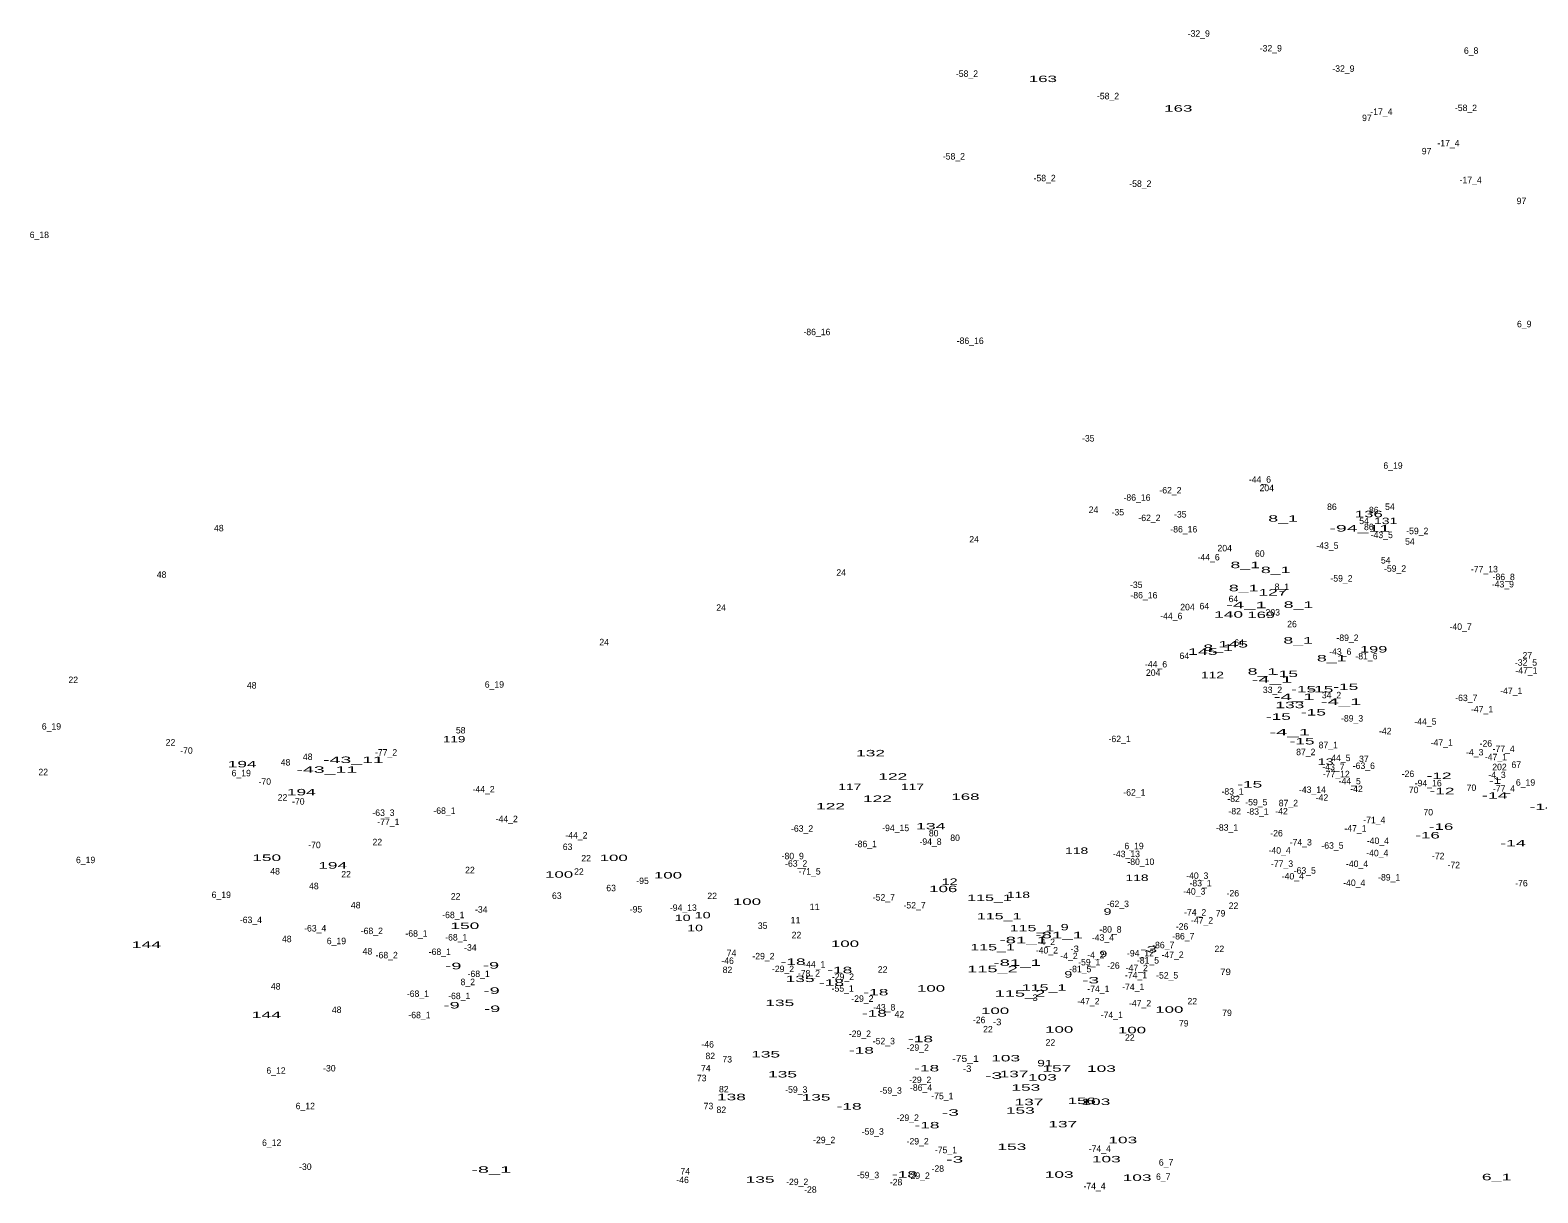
# Model space of a CAD drawing. Extents: x -659624 to -656248, y -1006345 to -1003555.
# Drawn here: x -658653 to -657721, y -1005012 to -1004293 of the extents above; entities that cross this region are included whole.
import ezdxf
from ezdxf.enums import TextEntityAlignment as Align

# ---------------------------------------------------------------- set-up
doc = ezdxf.new("R2010")
doc.units = 0
doc.header["$LTSCALE"] = 1.6
doc.layers.add('24', color=7, linetype='Continuous')

msp = doc.modelspace()

# ---------------------------------------------------------------- texts
at = {"layer": '24'}
for s, p in [('-32_9', (-657930.358, -1004297.46)), ('-32_9', (-657885.848, -1004306.59)), ('6_8', (-657762.051, -1004308.04)), ('-32_9', (-657840.968, -1004319.15)), ('-58_2', (-658073.602, -1004322.3)), ('-58_2', (-657986.432, -1004336.13)), ('-17_4', (-657817.496, -1004345.8)), ('-58_2', (-657765.232, -1004343.43)), ('97', (-657826.468, -1004349.62)), ('-17_4', (-657776.036, -1004365.21)), ('-58_2', (-658081.672, -1004373.38)), ('97', (-657789.558, -1004370.19)), ('-58_2', (-658025.602, -1004386.83)), ('-58_2', (-657966.462, -1004390.29)), ('-17_4', (-657762.346, -1004388.04)), ('97', (-657730.928, -1004400.96)), ('6_18', (-658646.834, -1004421.92)), ('6_9', (-657729.257, -1004477.04)), ('-86_16', (-658166.317, -1004481.95)), ('-86_16', (-658071.597, -1004487.39)), ('-35', (-657998.635, -1004547.69)), ('6_19', (-657810.32, -1004564.54)), ('-62_2', (-657947.868, -1004579.77)), ('-44_6', (-657892.556, -1004573.1)), ('204', (-657888.355, -1004578.38)), ('-86_16', (-657968.527, -1004584.28)), ('86', (-657848.083, -1004589.99)), ('54', (-657812.251, -1004589.97)), ('24', (-657995.401, -1004591.84)), ('-35', (-657980.385, -1004593.35)), ('-62_2', (-657960.828, -1004596.87)), ('-35', (-657941.775, -1004594.68)), ('54', (-657828.231, -1004598.73)), ('86', (-657822.223, -1004592.03)), ('48', (-658535.911, -1004603.2)), ('-86_16', (-657939.607, -1004603.89)), ('86', (-657825.273, -1004602.46)), ('-43_5', (-657817.267, -1004607.39)), ('-59_2', (-657795.318, -1004604.95)), ('24', (-658069.191, -1004610.09)), ('204', (-657914.315, -1004615.57)), ('-43_5', (-657850.857, -1004613.98)), ('54', (-657799.891, -1004611.47)), ('-44_6', (-657924.276, -1004621.18)), ('60', (-657892.637, -1004618.92)), ('54', (-657814.821, -1004623.08)), ('48', (-658571.281, -1004631.93)), ('24', (-658151.341, -1004630.65)), ('-59_2', (-657842.168, -1004634.24)), ('-59_2', (-657809.048, -1004628.19)), ('-77_13', (-657753.867, -1004628.55)), ('-86_8', (-657741.918, -1004633.36)), ('-35', (-657968.975, -1004638.24)), ('-86_16', (-657964.257, -1004644.67)), ('8_1', (-657879.03, -1004639.46)), ('-43_9', (-657742.442, -1004637.87)), ('24', (-658225.531, -1004652.33)), ('204', (-657937.335, -1004652)), ('64', (-657926.917, -1004651.4)), ('64', (-657908.937, -1004646.93)), ('203', (-657884.631, -1004655.24)), ('-44_6', (-657947.336, -1004657.52)), ('26', (-657872.743, -1004662.51)), ('-40_7', (-657768.556, -1004664.1)), ('24', (-658297.791, -1004673.64)), ('64', (-657905.417, -1004673.93)), ('-89_2', (-657838.438, -1004670.98)), ('64', (-657939.277, -1004682.12)), ('-43_6', (-657842.912, -1004679.52)), ('-81_6', (-657826.732, -1004682.36)), ('27', (-657727.313, -1004681.8)), ('-44_6', (-657956.756, -1004687.33)), ('204', (-657958.535, -1004692.53)), ('-32_5', (-657728.152, -1004686.27)), ('-47_1', (-657727.856, -1004691.19)), ('22', (-658625.877, -1004696.97)), ('48', (-658515.601, -1004700.39)), ('6_19', (-658365.63, -1004699.85)), ('33_2', (-657884.785, -1004703.16)), ('34_2', (-657848.32, -1004706.41)), ('-63_7', (-657765.024, -1004708.13)), ('-47_1', (-657737.256, -1004703.8)), ('-89_3', (-657835.608, -1004720.78)), ('-47_1', (-657755.286, -1004715.14)), ('6_19', (-658639.35, -1004725.77)), ('58', (-658386.457, -1004728.13)), ('-42', (-657815.099, -1004728.65)), ('-44_5', (-657790.301, -1004722.73)), ('22', (-658565.787, -1004735.6)), ('-62_1', (-657979.262, -1004733.51)), ('87_1', (-657850.334, -1004737.28)), ('-47_1', (-657780.206, -1004735.7)), ('-26', (-657752.96, -1004736.29)), ('-77_4', (-657741.938, -1004739.6)), ('-70', (-658555.924, -1004740.66)), ('48', (-658494.681, -1004747.95)), ('48', (-658480.991, -1004744.53)), ('-77_2', (-658432.564, -1004741.83)), ('87_2', (-657864.23, -1004741.56)), ('-44_5', (-657843.441, -1004745.23)), ('37', (-657828.343, -1004745.81)), ('-4_3', (-657759.818, -1004741.7)), ('-47_1', (-657746.766, -1004744.71)), ('22', (-658644.427, -1004753.95)), ('6_19', (-658522.08, -1004754.61)), ('-43_7', (-657847.122, -1004750.81)), ('-77_12', (-657845.387, -1004755.22)), ('-63_6', (-657828.343, -1004750.09)), ('-26', (-657801.09, -1004755.05)), ('-4_3', (-657746.028, -1004755.71)), ('202', (-657744.521, -1004750.86)), ('67', (-657734.158, -1004749.43)), ('-70', (-658507.534, -1004759.86)), ('-44_2', (-658372.311, -1004764.6)), ('-62_1', (-657970.142, -1004766.54)), ('-83_1', (-657909.496, -1004765.97)), ('-43_14', (-657860.135, -1004764.9)), ('-44_5', (-657837.091, -1004759.58)), ('-42', (-657832.879, -1004764.33)), ('70', (-657797.587, -1004765.02)), ('-94_16', (-657788.571, -1004760.82)), ('70', (-657761.837, -1004763.68)), ('-77_4', (-657741.748, -1004764.16)), ('6_19', (-657728.43, -1004760.4)), ('22', (-658496.557, -1004769.65)), ('-70', (-658486.794, -1004772.16)), ('-82', (-657908.835, -1004770.49)), ('-59_5', (-657894.778, -1004772.61)), ('87_2', (-657874.97, -1004773.15)), ('-42', (-657854.229, -1004769.72)), ('-63_3', (-658434.188, -1004779.12)), ('-77_1', (-658431.167, -1004784.8)), ('-68_1', (-658396.492, -1004777.86)), ('-44_2', (-658358.001, -1004782.97)), ('-82', (-657908.155, -1004778.16)), ('-83_1', (-657894.036, -1004778.35)), ('-42', (-657879.209, -1004778.18)), ('-71_4', (-657821.876, -1004783.62)), ('70', (-657788.557, -1004778.81)), ('-44_2', (-658314.931, -1004793.06)), ('-63_2', (-658175.498, -1004788.88)), ('-94_15', (-658117.666, -1004788.52)), ('80', (-658094.151, -1004791.77)), ('80', (-658080.931, -1004794.62)), ('-83_1', (-657912.866, -1004788.26)), ('-26', (-657882.3, -1004791.77)), ('-47_1', (-657833.516, -1004788.81)), ('-70', (-658476.814, -1004799.05)), ('22', (-658437.977, -1004797.24)), ('63', (-658320.413, -1004800.17)), ('-86_1', (-658136.092, -1004798.43)), ('-94_8', (-658096.122, -1004796.98)), ('-43_13', (-657975.03, -1004804.59)), ('6_19', (-657970.34, -1004799.69)), ('-40_4', (-657880.405, -1004802.4)), ('-74_3', (-657867.322, -1004797.36)), ('-63_5', (-657847.748, -1004799.37)), ('-40_4', (-657820.035, -1004804.04)), ('-40_4', (-657819.655, -1004796.44)), ('6_19', (-658618.23, -1004808.3)), ('22', (-658308.937, -1004807.23)), ('-80_9', (-658181.272, -1004805.9)), ('-63_2', (-658179.148, -1004810.49)), ('-80_10', (-657966.154, -1004809.43)), ('-77_3', (-657878.904, -1004810.63)), ('-40_4', (-657832.535, -1004810.67)), ('-72', (-657782.381, -1004805.88)), ('-72', (-657772.781, -1004811.45)), ('48', (-658501.151, -1004815.3)), ('22', (-658457.287, -1004817.12)), ('22', (-658380.737, -1004814.55)), ('22', (-658313.407, -1004815.5)), ('-95', (-658274.08, -1004821.23)), ('-71_5', (-658170.852, -1004815.35)), ('-40_3', (-657931.301, -1004818.05)), ('-83_1', (-657929.256, -1004822.62)), ('-40_4', (-657872.235, -1004818.37)), ('-63_5', (-657864.838, -1004814.83)), ('-40_4', (-657834.265, -1004822.4)), ('-89_1', (-657812.702, -1004819.04)), ('-76', (-657730.965, -1004822.67)), ('6_19', (-658534.42, -1004829.84)), ('48', (-658477.191, -1004824.43)), ('22', (-658389.577, -1004830.82)), ('63', (-658327.073, -1004830.42)), ('63', (-658293.503, -1004825.66)), ('22', (-658231.057, -1004830.54)), ('-52_7', (-658124.968, -1004831.41)), ('-40_3', (-657933.131, -1004827.74)), ('-26', (-657909.31, -1004828.87)), ('48', (-658451.321, -1004836.23)), ('-68_1', (-658391.022, -1004842.3)), ('-34', (-658373.729, -1004838.91)), ('-95', (-658278.15, -1004838.81)), ('-94_13', (-658248.906, -1004837.83)), ('-52_7', (-658105.968, -1004836.31)), ('-62_3', (-657980.348, -1004835.47)), ('-74_2', (-657932.582, -1004840.68)), ('79', (-657916.898, -1004841.27)), ('22', (-657908.877, -1004836.61)), ('-63_4', (-658516.112, -1004845.35)), ('-63_4', (-658476.372, -1004850.54)), ('35', (-658199.867, -1004848.94)), ('-80_8', (-657984.906, -1004851.24)), ('-26', (-657940.69, -1004849.42)), ('-47_2', (-657928.322, -1004845.67)), ('48', (-658493.921, -1004857.15)), ('6_19', (-658463.24, -1004858.38)), ('-68_2', (-658441.368, -1004852.15)), ('-68_1', (-658413.772, -1004853.73)), ('-68_1', (-658389.192, -1004856.13)), ('22', (-658178.947, -1004854.7)), ('-4_2', (-658024.538, -1004858.96)), ('-43_4', (-657989.561, -1004856.24)), ('-86_7', (-657952.314, -1004860.9)), ('-86_7', (-657939.894, -1004855.46)), ('48', (-658444.091, -1004864.76)), ('-68_2', (-658432.158, -1004867.13)), ('-68_1', (-658399.372, -1004865.06)), ('-34', (-658380.479, -1004862.41)), ('74', (-658219.087, -1004865.83)), ('-29_2', (-658199.358, -1004867.76)), ('-40_2', (-658024.211, -1004864.15)), ('-4_2', (-658010.558, -1004867.62)), ('-4_2', (-657993.958, -1004867.08)), ('-94_12', (-657966.396, -1004865.96)), ('-81_5', (-657961.756, -1004870.35)), ('-47_2', (-657946.552, -1004866.91)), ('22', (-657917.627, -1004863.25)), ('-68_1', (-658375.362, -1004878.71)), ('-46', (-658221.525, -1004870.59)), ('82', (-658221.607, -1004876.23)), ('-29_2', (-658187.278, -1004875.65)), ('-78_2', (-658171.268, -1004878.4)), ('-44_1', (-658167.955, -1004872.85)), ('22', (-658125.697, -1004876.01)), ('-81_5', (-658003.586, -1004875.74)), ('-59_1', (-657998.042, -1004871.5)), ('-26', (-657983.1, -1004873.58)), ('-74_1', (-657969.156, -1004879.48)), ('-47_2', (-657968.652, -1004875.06)), ('-52_5', (-657949.882, -1004879.63)), ('48', (-658500.771, -1004886.45)), ('8_2', (-658382.076, -1004883.73)), ('-55_1', (-658150.396, -1004887.72)), ('-29_2', (-658150.248, -1004880.51)), ('-74_1', (-657992.386, -1004887.93)), ('-74_1', (-657970.876, -1004886.78)), ('-68_1', (-658412.902, -1004891)), ('-68_1', (-658387.362, -1004892.35)), ('-29_2', (-658138.218, -1004894.02)), ('-47_2', (-657998.512, -1004895.61)), ('-47_2', (-657966.612, -1004896.88)), ('22', (-657934.367, -1004895.59)), ('48', (-658463.111, -1004900.91)), ('-68_1', (-658411.942, -1004904.16)), ('-43_8', (-658124.737, -1004899.39)), ('42', (-658115.381, -1004903.72)), ('-26', (-658066.07, -1004907.21)), ('-74_1', (-657984.126, -1004904.06)), ('79', (-657912.908, -1004902.79)), ('-29_2', (-658139.778, -1004915.75)), ('22', (-658060.647, -1004912.9)), ('79', (-657939.628, -1004909.26)), ('-46', (-658233.835, -1004922.27)), ('-52_3', (-658124.982, -1004920.27)), ('-29_2', (-658103.978, -1004924.26)), ('22', (-658022.037, -1004921.09)), ('22', (-657972.967, -1004918.04)), ('82', (-658232.227, -1004929.45)), ('73', (-658221.753, -1004931.51)), ('6_12', (-658500.564, -1004938.47)), ('-30', (-658467.619, -1004937.05)), ('73', (-658237.543, -1004943.12)), ('74', (-658234.977, -1004937.03)), ('-29_2', (-658102.468, -1004944.23)), ('82', (-658223.857, -1004950)), ('-59_3', (-658179.068, -1004950.24)), ('-59_3', (-658120.698, -1004950.82)), ('-86_4', (-658101.972, -1004948.99)), ('6_12', (-658482.484, -1004960.39)), ('73', (-658233.353, -1004960.43)), ('82', (-658225.387, -1004962.74)), ('-75_1', (-658088.832, -1004954.21)), ('-29_2', (-658110.168, -1004967.63)), ('-29_2', (-658161.838, -1004981.39)), ('-59_3', (-658131.828, -1004976.17)), ('6_12', (-658503.244, -1004983.09)), ('-29_2', (-658104.078, -1004982.19)), ('-75_1', (-658086.602, -1004987.61)), ('-74_4', (-657991.506, -1004986.75)), ('-30', (-658482.449, -1004997.93)), ('-28', (-658091.635, -1004999.08)), ('6_7', (-657950.567, -1004995.23)), ('-46', (-658249.345, -1005006.06)), ('74', (-658247.717, -1005000.76)), ('-29_2', (-658178.518, -1005007.3)), ('-59_3', (-658134.708, -1005003.06)), ('-28', (-658117.405, -1005007.45)), ('-29_2', (-658103.418, -1005003.49)), ('-74_4', (-657994.776, -1005009.89)), ('6_7', (-657952.297, -1005004.08)), ('-28', (-658170.365, -1005012.03))]:
    msp.add_text(s, height=4, dxfattribs=at).set_placement(p, align=Align.CENTER)
for s, width, p in [('163', 1.95, (-658026.693, -1004325.51)), ('163', 1.95, (-657943.013, -1004343.77)), ('8_1', 2.05, (-657878.259, -1004597.24)), ('136', 1.95, (-657825.303, -1004594.48)), ('131', 1.6, (-657814.864, -1004598.76)), ('-94_11', 2.25, (-657830.878, -1004603.33)), ('8_1', 2.05, (-657901.649, -1004625.96)), ('8_1', 2.05, (-657882.819, -1004629.01)), ('8_1', 2.05, (-657902.599, -1004640.23)), ('127', 2, (-657884.513, -1004642.88)), ('-4_1', 2.35, (-657900.907, -1004650.7)), ('8_1', 2.05, (-657868.739, -1004650.51)), ('140', 2, (-657911.919, -1004656.56)), ('169', 1.9, (-657891.747, -1004656.8)), ('8_1', 2.05, (-657868.939, -1004672.57)), ('145', 2.05, (-657927.813, -1004679.55)), ('8_1', 2.05, (-657918.379, -1004677.14)), ('145', 2.05, (-657909.073, -1004674.99)), ('8_1', 2.05, (-657848.209, -1004683.61)), ('199', 1.9, (-657822.287, -1004678.1)), ('8_1', 2.05, (-657890.999, -1004691.79)), ('-15', 2, (-657876.791, -1004693.26)), ('112', 1.6, (-657921.934, -1004694)), ('-4_1', 2.35, (-657885.117, -1004696.78)), ('-15', 2, (-657839.511, -1004701.25)), ('-4_1', 2.35, (-657871.417, -1004707.44)), ('-15', 2, (-657865.561, -1004702.77)), ('-15', 2, (-657854.911, -1004702.77)), ('-4_1', 2.35, (-657842.417, -1004710.48)), ('-15', 2, (-657881.161, -1004719.71)), ('133', 2, (-657874.067, -1004712.5)), ('-15', 2, (-657859.481, -1004717.04)), ('-4_1', 2.35, (-657874.177, -1004729.32)), ('119', 1.55, (-658390.479, -1004733.67)), ('-15', 2, (-657866.521, -1004734.93)), ('194', 2, (-658521.488, -1004749.09)), ('-43_11', 2.25, (-658452.753, -1004746.4)), ('132', 2, (-658133.167, -1004742.29)), ('13', 1.65, (-657851.947, -1004747.57)), ('-43_11', 2.25, (-658469.183, -1004752.46)), ('122', 2, (-658119.427, -1004756.71)), ('-12', 2, (-657781.891, -1004756.29)), ('194', 2, (-658484.968, -1004766.4)), ('117', 1.6, (-658146.039, -1004763.15)), ('117', 1.6, (-658107.309, -1004763.15)), ('-15', 2, (-657898.851, -1004761.56)), ('-12', 2, (-657780.081, -1004765.71)), ('-1', 1.55, (-657747.311, -1004759.28)), ('122', 2, (-658157.877, -1004775.08)), ('122', 2, (-658128.947, -1004770.46)), ('168', 1.95, (-658074.553, -1004769.2)), ('-14', 2.05, (-657747.386, -1004768.45)), ('-14', 2.05, (-657718.096, -1004775.49)), ('134', 2.05, (-658095.963, -1004787.46)), ('-16', 1.95, (-657788.945, -1004793.04)), ('-16', 1.95, (-657780.585, -1004787.71)), ('118', 1.6, (-658005.814, -1004802.58)), ('-14', 2.05, (-657736.166, -1004797.94)), ('150', 2, (-658506.344, -1004806.93)), ('194', 2, (-658465.578, -1004811.68)), ('100', 1.95, (-658291.91, -1004807.01)), ('100', 1.95, (-658325.65, -1004817.3)), ('100', 1.95, (-658258.37, -1004817.78)), ('12', 1.65, (-658084.317, -1004821.75)), ('118', 1.6, (-657968.524, -1004819.31)), ('106', 1.95, (-658088.239, -1004826.21)), ('115_1', 1.85, (-658059.671, -1004831.67)), ('118', 1.6, (-658041.764, -1004829.88)), ('100', 1.95, (-658209.54, -1004834.12)), ('11', 1.05, (-658167.744, -1004837.33)), ('9', 1.65, (-657986.776, -1004840.25)), ('150', 2, (-658383.874, -1004848.98)), ('10', 1.65, (-658249.284, -1004844.08)), ('10', 1.65, (-658241.584, -1004850.36)), ('10', 1.65, (-658236.924, -1004842.41)), ('11', 1.05, (-658179.534, -1004845.51)), ('115_1', 1.85, (-658053.711, -1004843.02)), ('115_1', 1.85, (-658033.431, -1004850.42)), ('9', 1.65, (-658013.216, -1004849.85)), ('144', 2.05, (-658580.699, -1004860.67)), ('100', 1.95, (-658148.97, -1004860.1)), ('-81_1', 2.15, (-658038.807, -1004857.79)), ('-81_1', 2.15, (-658016.577, -1004854.69)), ('115_1', 1.85, (-658057.751, -1004862.25)), ('-3', 1.1, (-658007.06, -1004863.25)), ('9', 1.65, (-657989.346, -1004866.41)), ('-3', 2.2, (-657961.284, -1004863.51)), ('-9', 2.1, (-658391.009, -1004873.86)), ('-9', 2.1, (-658367.709, -1004873.48)), ('-18', 2, (-658181.041, -1004871.2)), ('-18', 2, (-658152.201, -1004876.35)), ('115_2', 2.1, (-658057.845, -1004875.72)), ('-81_1', 2.15, (-658042.537, -1004871.77)), ('9', 1.65, (-658010.976, -1004879.03)), ('79', 1.1, (-657913.79, -1004877.49)), ('135', 2, (-658176.717, -1004881.81)), ('-18', 2, (-658157.321, -1004884.1)), ('100', 1.95, (-658095.8, -1004887.7)), ('115_1', 1.85, (-658025.931, -1004887.16)), ('-3', 2.2, (-657997.204, -1004882.62)), ('-9', 2.1, (-658392.049, -1004898.12)), ('-9', 2.1, (-658367.329, -1004889.08)), ('135', 2, (-658189.267, -1004896.65)), ('-18', 2, (-658129.881, -1004890.04)), ('115_2', 2.1, (-658040.835, -1004890.81)), ('-3', 1.1, (-658032.5, -1004893.46)), ('144', 2.05, (-658506.529, -1004904.05)), ('-9', 2.1, (-658367.039, -1004900.3)), ('-18', 2, (-658130.831, -1004903.16)), ('100', 1.95, (-658056.2, -1004901.55)), ('100', 1.95, (-657948.55, -1004900.78)), ('-3', 1.1, (-658054.95, -1004908.48)), ('100', 1.95, (-658016.6, -1004913.09)), ('100', 1.95, (-657971.62, -1004913.47)), ('-18', 2, (-658138.821, -1004925.99)), ('-18', 2, (-658102.311, -1004918.96)), ('135', 2, (-658198.017, -1004928.42)), ('-75_1', 1.2, (-658074.5, -1004931.11)), ('103', 2, (-658049.694, -1004930.85)), ('91', 1.6, (-658025.463, -1004933.9)), ('135', 2, (-658187.557, -1004940.78)), ('-18', 2, (-658098.501, -1004937.03)), ('-3', 1.1, (-658073.49, -1004937.34)), ('-3', 2.2, (-658057.104, -1004941.58)), ('137', 2, (-658044.533, -1004940.61)), ('103', 2, (-658027.014, -1004942.67)), ('157', 2, (-658018.043, -1004937.18)), ('103', 2, (-657990.484, -1004937.29)), ('153', 2, (-658037.217, -1004948.97)), ('138', 2, (-658219.147, -1004954.84)), ('135', 2, (-658166.827, -1004955.05)), ('-18', 2, (-658146.431, -1004960.62)), ('153', 2, (-658040.637, -1004963.14)), ('137', 2, (-658035.303, -1004957.93)), ('156', 1.95, (-658002.683, -1004957.22)), ('103', 2, (-657993.944, -1004957.77)), ('-18', 2, (-658098.311, -1004972.23)), ('-3', 2.2, (-658083.824, -1004964.41)), ('137', 2, (-658014.383, -1004971.62)), ('103', 2, (-657977.314, -1004981.42)), ('153', 2, (-658045.867, -1004985.59)), ('-8_1', 2.3, (-658367.591, -1004999.69)), ('-3', 2.2, (-658081.164, -1004993.43)), ('103', 2, (-657987.504, -1004993.25)), ('135', 2, (-658201.437, -1005005.85)), ('-18', 2, (-658112.201, -1005002.67)), ('103', 2, (-658016.624, -1005002.77)), ('103', 2, (-657968.464, -1005004.69)), ('6_1', 2.05, (-657746.303, -1005004.3))]:
    msp.add_text(s, height=4, dxfattribs=dict(at, width=width)).set_placement(p, align=Align.CENTER)

doc.saveas('drawing.dxf')
